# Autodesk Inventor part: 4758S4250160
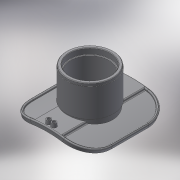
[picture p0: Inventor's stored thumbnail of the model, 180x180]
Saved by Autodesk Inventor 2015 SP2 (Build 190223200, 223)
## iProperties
Created: 2017-08
Part Number: 4758S4250160
Material: Generic
Description: PLASSON WASTEWATER SADDLE 225-250X160 SPIGOT INLET
Document SubType Name: Modeling
Designer: Кирилл
Density: 1 g/cm^3
Appearance: Default
Author: Кирилл
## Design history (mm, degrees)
derived "4758S4.ipt"
feature "Solid1::4758S4.ipt"
feature "Solid2::4758S4.ipt"
feature "Solid3::4758S4.ipt"
tag "TaggingFeature1"
body "Solid1"
other parameters: "d1" = 225, "d2" = 275, "d4" = 0, "d5" = 67.5, "d6" = 8, "d7" = 30 deg, "d8" = 15 deg, "d10" = 0, "d11" = 162.5, "d38" = 1.25, "d40" = 151, "d41" = 15, "d42" = 130.5, "d43" = 17.6, "d44" = 8.8, "d46" = 5 deg, "d47" = 4, "d49" = 4, "d51" = 14, "d52" = 0, "d53" = 3, "d54" = 0, "d75" = 0, "d77" = 0, "d78" = 1.6, "d82" = 125, "d84" = 156.8, "d85" = 128, "d86" = 136, "d87" = 18.75, "d88" = 152, "d89" = 18.75, "d90" = 9.375, "d91" = 1.6, "B_" = 225, "H_" = 125
